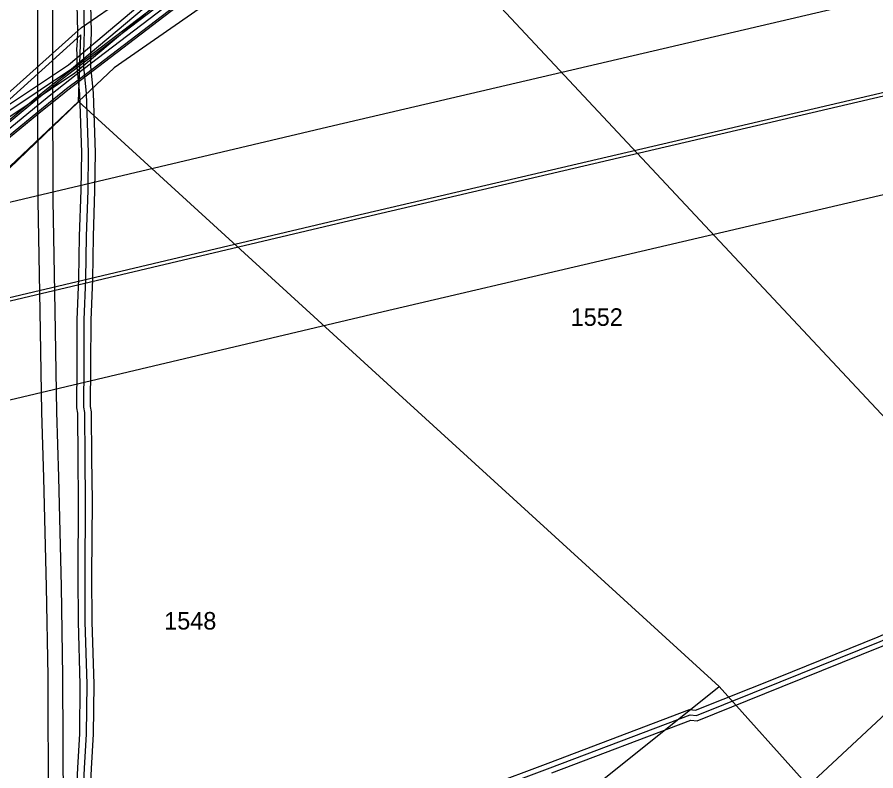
# Model space of a CAD drawing. Extents: x -510185 to -506993, y -1126306 to -1123642.
# Drawn here: x -509788.7 to -509538.9, y -1125355.5 to -1125136.3 of the extents above; entities that cross this region are included whole.
import ezdxf

# ---------------------------------------------------------------- set-up
doc = ezdxf.new("R2010")
doc.units = 0
for name, color, linetype in [('Net4gas', 7, 'Continuous'), ('parcelni hranice', 7, 'Continuous'), ('popis cesty', 7, 'Continuous'), ('telefonica', 7, 'Continuous'), ('u_cesta19', 7, 'Continuous'), ('u_kabely', 7, 'Continuous'), ('u_net4gas', 7, 'Continuous'), ('u_osa19', 7, 'Continuous'), ('u_sitel_self_net4', 7, 'Continuous'), ('u_Telefonica', 7, 'Continuous'), ('u_vysadba_oseti', 7, 'Continuous'), ('u_ČEPS nadzemní VVN', 7, 'Continuous'), ('ČEPS', 7, 'Continuous'), ('ˇ2', 7, 'Continuous')]:
    doc.layers.add(name, color=color, linetype=linetype)

msp = doc.modelspace()

# ---------------------------------------------------------------- linework, layer by layer
at = {"layer": 'Net4gas'}
for points in [[(-509778.35, -1125154.75), (-509778.44, -1125113.23), (-509778.46, -1125091.17), (-509778.75, -1125046.37), (-509778.62, -1125017.65)], [(-509778.14, -1125384.1), (-509776.59, -1125380.08), (-509775.27, -1125366.56), (-509775.4, -1125327.96), (-509775.81, -1125301.88), (-509776.64, -1125270.13), (-509777.19, -1125251.11), (-509777.71, -1125221.73), (-509778.27, -1125189.62), (-509778.35, -1125154.75)]]:
    msp.add_lwpolyline(points, dxfattribs=at)
at = {"layer": 'parcelni hranice'}
for p, q in [((-509686.79, -1125091.92), (-509590.02, -1125195.38)), ((-509769.97, -1125139.3), (-509728.28, -1125110.29)), ((-509718.82, -1125121.98), (-509760.48, -1125150.97)), ((-509800.85, -1125166.88), (-509769.97, -1125139.3)), ((-509770.9, -1125160.82), (-509760.48, -1125150.97)), ((-509770.9, -1125160.82), (-509822.85, -1125209.93)), ((-509770.9, -1125160.82), (-509677.67, -1125245.92)), ((-509493.26, -1125298.85), (-509590.02, -1125195.38)), ((-509677.67, -1125245.92), (-509584.44, -1125331.01)), ((-509558.57, -1125359.93), (-509516.43, -1125320.52)), ((-509740.65, -1125455.59), (-509584.44, -1125331.01)), ((-509584.44, -1125331.01), (-509558.57, -1125359.93))]:
    msp.add_line(p, q, dxfattribs=at)
at = {"layer": 'telefonica'}
for points in [[(-509694.35, -1125080.09), (-509696.45, -1125081.99), (-509731.6, -1125114.65), (-509773.78, -1125150.19), (-509801.48, -1125168.63), (-509803.07, -1125169.68)], [(-509692.34, -1125082.31), (-509694.42, -1125084.2), (-509729.61, -1125116.9), (-509771.98, -1125152.59), (-509799.82, -1125171.13), (-509801.4, -1125172.18)], [(-509670.5, -1125366.82), (-509634.2, -1125353.26), (-509593.11, -1125337.71), (-509591.33, -1125337.92), (-509567.26, -1125328.25), (-509538.2, -1125316.54), (-509500.12, -1125299.96), (-509478.28, -1125291.92), (-509437.88, -1125275.72), (-509398.79, -1125260.35), (-509359.94, -1125246.23), (-509345.01, -1125240.97), (-509320.97, -1125233.28), (-509308.13, -1125229.32), (-509295.01, -1125225.85), (-509287.08, -1125224.01), (-509271.69, -1125220.81), (-509264.16, -1125218.89), (-509261.85, -1125218.29), (-509239.91, -1125211.9), (-509199.74, -1125200.42), (-509198.86, -1125200.12), (-509151.58, -1125189.73)], [(-509633.14, -1125356.06), (-509592.73, -1125340.77), (-509590.91, -1125340.98), (-509566.14, -1125331.03), (-509537.04, -1125319.3), (-509499, -1125302.74), (-509477.2, -1125294.72), (-509436.78, -1125278.5), (-509397.73, -1125263.15), (-509358.92, -1125249.05), (-509344.05, -1125243.81), (-509320.07, -1125236.14), (-509307.31, -1125232.2), (-509294.29, -1125228.77), (-509286.44, -1125226.93), (-509271.01, -1125223.73), (-509263.42, -1125221.79), (-509261.05, -1125221.19), (-509239.07, -1125214.78), (-509198.84, -1125203.28), (-509198.06, -1125203.02), (-509150.9, -1125192.65)]]:
    msp.add_lwpolyline(points, dxfattribs=at)
at = {"layer": 'u_cesta19'}
for points in [[(-509794.86, -1125169.23), (-509783.89, -1125160.23), (-509780.21, -1125157.24), (-509776.49, -1125154.29), (-509772.74, -1125151.39), (-509715.44, -1125107.62), (-509706.4, -1125100.56), (-509697.53, -1125093.32), (-509688.81, -1125085.88), (-509680.26, -1125078.26), (-509671.86, -1125070.45), (-509644.06, -1125044.01), (-509634.75, -1125035.23), (-509625.37, -1125026.51), (-509615.92, -1125017.87), (-509572.36, -1124978.38), (-509561.9, -1124968.89), (-509551.43, -1124959.4), (-509540.97, -1124949.91), (-509520.04, -1124930.93), (-509513.04, -1124924.62), (-509506.01, -1124918.34), (-509498.96, -1124912.09), (-509455.78, -1124874.01)], [(-509794.86, -1125169.23), (-509783.89, -1125160.23), (-509780.21, -1125157.24), (-509776.49, -1125154.29), (-509772.74, -1125151.39), (-509715.44, -1125107.62), (-509706.4, -1125100.56), (-509697.53, -1125093.32), (-509688.81, -1125085.88), (-509680.26, -1125078.26), (-509671.86, -1125070.45), (-509644.06, -1125044.01), (-509634.75, -1125035.23), (-509625.37, -1125026.51), (-509615.92, -1125017.87), (-509572.36, -1124978.38), (-509561.9, -1124968.89), (-509551.43, -1124959.4), (-509540.97, -1124949.91), (-509520.04, -1124930.93), (-509513.04, -1124924.62), (-509506.01, -1124918.34), (-509498.96, -1124912.09), (-509455.78, -1124874.01)], [(-509794.54, -1125169.62), (-509783.58, -1125160.61), (-509779.9, -1125157.63), (-509776.18, -1125154.68), (-509772.43, -1125151.79), (-509715.13, -1125108.02), (-509706.09, -1125100.95), (-509697.21, -1125093.7), (-509688.48, -1125086.26), (-509679.92, -1125078.63), (-509671.52, -1125070.81), (-509643.72, -1125044.37), (-509634.41, -1125035.59), (-509625.03, -1125026.88), (-509615.58, -1125018.24), (-509572.03, -1124978.75), (-509561.56, -1124969.26), (-509551.1, -1124959.77), (-509540.63, -1124950.28), (-509519.7, -1124931.3), (-509512.71, -1124924.99), (-509505.68, -1124918.71), (-509498.63, -1124912.46), (-509455.45, -1124874.39)], [(-509792.62, -1125171.93), (-509781.68, -1125162.94), (-509778.02, -1125159.97), (-509774.33, -1125157.05), (-509770.61, -1125154.17), (-509713.3, -1125110.39), (-509704.22, -1125103.3), (-509695.28, -1125096), (-509686.51, -1125088.52), (-509677.9, -1125080.85), (-509669.46, -1125073), (-509641.66, -1125046.55), (-509632.36, -1125037.78), (-509623, -1125029.09), (-509613.56, -1125020.46), (-509570.01, -1124980.97), (-509559.55, -1124971.48), (-509549.08, -1124961.99), (-509538.62, -1124952.5), (-509517.69, -1124933.53), (-509510.7, -1124927.22), (-509503.69, -1124920.95), (-509496.64, -1124914.71), (-509453.47, -1124876.64)], [(-509792.3, -1125172.31), (-509781.36, -1125163.32), (-509777.71, -1125160.36), (-509774.02, -1125157.44), (-509770.3, -1125154.56), (-509742.35, -1125133.21)]]:
    msp.add_lwpolyline(points, dxfattribs=at)
at = {"layer": 'u_kabely'}
for points in [[(-509771.8, -1125368.4), (-509771.12, -1125354.61), (-509770.52, -1125344.76), (-509770.36, -1125330.37), (-509770.9, -1125312.2), (-509770.96, -1125298.81), (-509770.84, -1125276.96), (-509770.97, -1125264.71), (-509771.06, -1125251.51), (-509771.37, -1125249.91), (-509771.27, -1125237.36), (-509771.23, -1125224.29), (-509770.75, -1125212.37), (-509770.55, -1125199.95), (-509770.09, -1125186.6), (-509769.93, -1125175.65), (-509770.53, -1125158.63), (-509771.31, -1125150.67), (-509771.29, -1125147.12), (-509771.33, -1125145.44), (-509771.26, -1125144.6), (-509771.2, -1125143.04), (-509771.1, -1125140.55), (-509771.74, -1125112.71)], [(-509767.8, -1125368.5), (-509767.12, -1125354.83), (-509766.52, -1125344.9), (-509766.36, -1125330.33), (-509766.9, -1125312.14), (-509766.96, -1125298.81), (-509766.84, -1125276.94), (-509766.97, -1125264.67), (-509767.06, -1125251.11), (-509767.37, -1125249.53), (-509767.27, -1125237.38), (-509767.23, -1125224.37), (-509766.75, -1125212.49), (-509766.55, -1125200.05), (-509766.09, -1125186.7), (-509765.93, -1125175.61), (-509766.53, -1125158.37), (-509767.31, -1125150.48), (-509767.29, -1125147.08), (-509767.33, -1125145.56), (-509767.27, -1125144.84), (-509767.2, -1125143.2), (-509767.1, -1125140.59), (-509767.74, -1125112.57)]]:
    msp.add_lwpolyline(points, dxfattribs=at)
at = {"layer": 'u_net4gas'}
for points in [[(-509782.7, -1125154.76), (-509782.79, -1125113.23), (-509782.81, -1125091.19), (-509783.1, -1125046.37), (-509782.97, -1125017.63)], [(-509782.2, -1125382.53), (-509780.86, -1125379.06), (-509779.62, -1125366.36), (-509779.75, -1125328), (-509780.16, -1125301.97), (-509780.98, -1125270.26), (-509781.54, -1125251.21), (-509782.06, -1125221.81), (-509782.62, -1125189.67), (-509782.7, -1125154.76)]]:
    msp.add_lwpolyline(points, dxfattribs=at)
at = {"layer": 'u_osa19'}
msp.add_lwpolyline([(-509793.58, -1125170.77), (-509782.63, -1125161.78), (-509778.96, -1125158.8), (-509775.26, -1125155.87), (-509771.52, -1125152.98), (-509714.21, -1125109.2), (-509705.15, -1125102.13), (-509696.24, -1125094.85), (-509687.5, -1125087.39), (-509678.91, -1125079.74), (-509670.49, -1125071.9), (-509642.69, -1125045.46), (-509633.38, -1125036.69), (-509624.01, -1125027.98), (-509614.57, -1125019.35), (-509571.02, -1124979.86), (-509560.56, -1124970.37), (-509550.09, -1124960.88), (-509539.63, -1124951.39), (-509518.7, -1124932.42), (-509511.7, -1124926.11), (-509504.68, -1124919.83), (-509497.63, -1124913.59), (-509454.46, -1124875.51)], dxfattribs=at)
msp.add_lwpolyline([(-509793.58, -1125170.77), (-509782.63, -1125161.78), (-509778.96, -1125158.8), (-509775.26, -1125155.87), (-509771.52, -1125152.98), (-509714.21, -1125109.2), (-509705.15, -1125102.13), (-509696.24, -1125094.85), (-509687.5, -1125087.39), (-509678.91, -1125079.74), (-509670.49, -1125071.9), (-509642.69, -1125045.46), (-509633.38, -1125036.69), (-509624.01, -1125027.98), (-509614.57, -1125019.35), (-509571.02, -1124979.86), (-509560.56, -1124970.37), (-509550.09, -1124960.88), (-509539.63, -1124951.39), (-509518.7, -1124932.42), (-509511.7, -1124926.11), (-509504.68, -1124919.83), (-509497.63, -1124913.59), (-509454.46, -1124875.51)], dxfattribs=at)
at = {"layer": 'u_sitel_self_net4'}
msp.add_lwpolyline([(-509769.8, -1125368.45), (-509769.12, -1125354.72), (-509768.52, -1125344.83), (-509768.36, -1125330.35), (-509768.9, -1125312.17), (-509768.96, -1125298.81), (-509768.84, -1125276.95), (-509768.97, -1125264.69), (-509769.06, -1125251.31), (-509769.37, -1125249.72), (-509769.27, -1125237.37), (-509769.23, -1125224.33), (-509768.75, -1125212.43), (-509768.55, -1125200), (-509768.09, -1125186.65), (-509767.93, -1125175.63), (-509768.53, -1125158.5), (-509769.31, -1125150.57), (-509769.29, -1125147.1), (-509769.33, -1125145.5), (-509769.27, -1125144.72), (-509769.2, -1125143.12), (-509769.1, -1125140.57), (-509769.74, -1125112.64)], dxfattribs=at)
msp.add_lwpolyline([(-509769.8, -1125368.45), (-509769.12, -1125354.72), (-509768.52, -1125344.83), (-509768.36, -1125330.35), (-509768.9, -1125312.17), (-509768.96, -1125298.81), (-509768.84, -1125276.95), (-509768.97, -1125264.69), (-509769.06, -1125251.31), (-509769.37, -1125249.72), (-509769.27, -1125237.37), (-509769.23, -1125224.33), (-509768.75, -1125212.43), (-509768.55, -1125200), (-509768.09, -1125186.65), (-509767.93, -1125175.63), (-509768.53, -1125158.5), (-509769.31, -1125150.57), (-509769.29, -1125147.1), (-509769.33, -1125145.5), (-509769.27, -1125144.72), (-509769.2, -1125143.12), (-509769.1, -1125140.57), (-509769.74, -1125112.64)], dxfattribs=at)
msp.add_lwpolyline([(-509769.8, -1125368.45), (-509769.12, -1125354.72), (-509768.52, -1125344.83), (-509768.36, -1125330.35), (-509768.9, -1125312.17), (-509768.96, -1125298.81), (-509768.84, -1125276.95), (-509768.97, -1125264.69), (-509769.06, -1125251.31), (-509769.37, -1125249.72), (-509769.27, -1125237.37), (-509769.23, -1125224.33), (-509768.75, -1125212.43), (-509768.55, -1125200), (-509768.09, -1125186.65), (-509767.93, -1125175.63), (-509768.53, -1125158.5), (-509769.31, -1125150.57), (-509769.29, -1125147.1), (-509769.33, -1125145.5), (-509769.27, -1125144.72), (-509769.2, -1125143.12), (-509769.1, -1125140.57), (-509769.74, -1125112.64)], dxfattribs=at)
at = {"layer": 'u_Telefonica'}
for points in [[(-509693.34, -1125081.2), (-509695.43, -1125083.09), (-509730.61, -1125115.78), (-509772.88, -1125151.39), (-509800.65, -1125169.88), (-509802.23, -1125170.93)], [(-509693.34, -1125081.2), (-509695.43, -1125083.09), (-509730.61, -1125115.78), (-509772.88, -1125151.39), (-509800.65, -1125169.88), (-509802.23, -1125170.93)], [(-509669.97, -1125368.22), (-509633.67, -1125354.66), (-509592.92, -1125339.24), (-509591.12, -1125339.45), (-509566.7, -1125329.64), (-509537.62, -1125317.92), (-509499.56, -1125301.35), (-509477.74, -1125293.32), (-509437.33, -1125277.11), (-509398.26, -1125261.75), (-509359.43, -1125247.64), (-509344.53, -1125242.39), (-509320.52, -1125234.71), (-509307.72, -1125230.76), (-509294.65, -1125227.31), (-509286.76, -1125225.47), (-509271.35, -1125222.27), (-509263.79, -1125220.34), (-509261.45, -1125219.74), (-509239.49, -1125213.34), (-509199.29, -1125201.85), (-509198.46, -1125201.57), (-509151.24, -1125191.19)], [(-509669.97, -1125368.22), (-509633.67, -1125354.66), (-509592.92, -1125339.24), (-509591.12, -1125339.45), (-509566.7, -1125329.64), (-509537.62, -1125317.92), (-509499.56, -1125301.35), (-509477.74, -1125293.32), (-509437.33, -1125277.11), (-509398.26, -1125261.75), (-509359.43, -1125247.64), (-509344.53, -1125242.39), (-509320.52, -1125234.71), (-509307.72, -1125230.76), (-509294.65, -1125227.31), (-509286.76, -1125225.47), (-509271.35, -1125222.27), (-509263.79, -1125220.34), (-509261.45, -1125219.74), (-509239.49, -1125213.34), (-509199.29, -1125201.85), (-509198.46, -1125201.57), (-509151.24, -1125191.19)], [(-509669.97, -1125368.22), (-509633.67, -1125354.66), (-509592.92, -1125339.24), (-509591.12, -1125339.45), (-509566.7, -1125329.64), (-509537.62, -1125317.92), (-509499.56, -1125301.35), (-509477.74, -1125293.32), (-509437.33, -1125277.11), (-509398.26, -1125261.75), (-509359.43, -1125247.64), (-509344.53, -1125242.39), (-509320.52, -1125234.71), (-509307.72, -1125230.76), (-509294.65, -1125227.31), (-509286.76, -1125225.47), (-509271.35, -1125222.27), (-509263.79, -1125220.34), (-509261.45, -1125219.74), (-509239.49, -1125213.34), (-509199.29, -1125201.85), (-509198.46, -1125201.57), (-509151.24, -1125191.19)], [(-509669.97, -1125368.22), (-509633.67, -1125354.66), (-509592.92, -1125339.24), (-509591.12, -1125339.45), (-509566.7, -1125329.64), (-509537.62, -1125317.92), (-509499.56, -1125301.35), (-509477.74, -1125293.32), (-509437.33, -1125277.11), (-509398.26, -1125261.75), (-509359.43, -1125247.64), (-509344.53, -1125242.39), (-509320.52, -1125234.71), (-509307.72, -1125230.76), (-509294.65, -1125227.31), (-509286.76, -1125225.47), (-509271.35, -1125222.27), (-509263.79, -1125220.34), (-509261.45, -1125219.74), (-509239.49, -1125213.34), (-509199.29, -1125201.85), (-509198.46, -1125201.57), (-509151.24, -1125191.19)]]:
    msp.add_lwpolyline(points, dxfattribs=at)
at = {"layer": 'u_vysadba_oseti'}
msp.add_lwpolyline([(-509939.54, -1125282.93), (-509907.24, -1125275.04), (-509861.8, -1125241.99), (-509818.61, -1125206.69), (-509770.92, -1125160.88), (-509770.17, -1125141.35), (-509849.78, -1125213.45), (-509923.01, -1125267.91)], close=True, dxfattribs=at)
at = {"layer": 'u_ČEPS nadzemní VVN'}
for points in [[(-510185.05, -1125336.69), (-510011.44, -1125269.94), (-509690.54, -1125194.07), (-509367.08, -1125118.37), (-509051.23, -1125043.52), (-508723.83, -1124966.6), (-508395.54, -1124892.88), (-508077.37, -1124819.87), (-507910.72, -1124779.68)], [(-510185.05, -1125337.76), (-510011.14, -1125270.9), (-509690.31, -1125195.05), (-509366.85, -1125119.34), (-509051.01, -1125044.5), (-508723.61, -1124967.57), (-508395.32, -1124893.85), (-508077.14, -1124820.84), (-507910.72, -1124780.71)]]:
    msp.add_lwpolyline(points, dxfattribs=at)
at = {"layer": 'ČEPS'}
for points in [[(-510185.05, -1125307.76), (-510019.43, -1125244.08), (-509696.72, -1125167.79), (-509373.27, -1125092.09), (-509057.44, -1125017.25), (-508729.88, -1124940.28), (-508401.51, -1124866.55), (-508083.55, -1124793.59), (-507890, -1124746.91)], [(-510185.05, -1125367.76), (-510002.86, -1125297.71), (-509683.9, -1125222.3), (-509360.43, -1125146.6), (-509044.57, -1125071.75), (-508717.34, -1124994.86), (-508389.12, -1124921.16), (-508070.72, -1124848.1), (-507890, -1124804.52)]]:
    msp.add_lwpolyline(points, dxfattribs=at)

# ---------------------------------------------------------------- texts
at = {"layer": 'popis cesty'}
msp.add_text('SO21 Polní cesta PC 19 - dl. 658 m', height=15, rotation=40.0005, dxfattribs=at).set_placement((-509980.35, -1125283.07))
at = {"layer": 'ˇ2'}
for s, p in [('1552', (-509627.69, -1125226.06)), ('1548', (-509745.95, -1125314.42))]:
    msp.add_text(s, height=5.1, dxfattribs=at).set_placement(p)

doc.saveas('drawing.dxf')
